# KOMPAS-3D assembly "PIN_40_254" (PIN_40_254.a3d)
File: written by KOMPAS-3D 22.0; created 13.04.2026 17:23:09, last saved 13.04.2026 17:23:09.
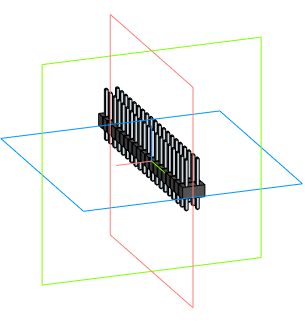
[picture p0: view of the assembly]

Document properties: Автор: Andrey; Полное имя файла: C:\Users\User1\Documents\PIN_40_254.a3d

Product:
- Component [assembly]: ASSEMBLY  | qty 1  | source file: ASSEMBLY_19.a3d
- Part/product: PIN_40_254
    Комментарий: PIN_40_254

Referenced files in C:\Users\User1\Documents\: ASSEMBLY_19.a3d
